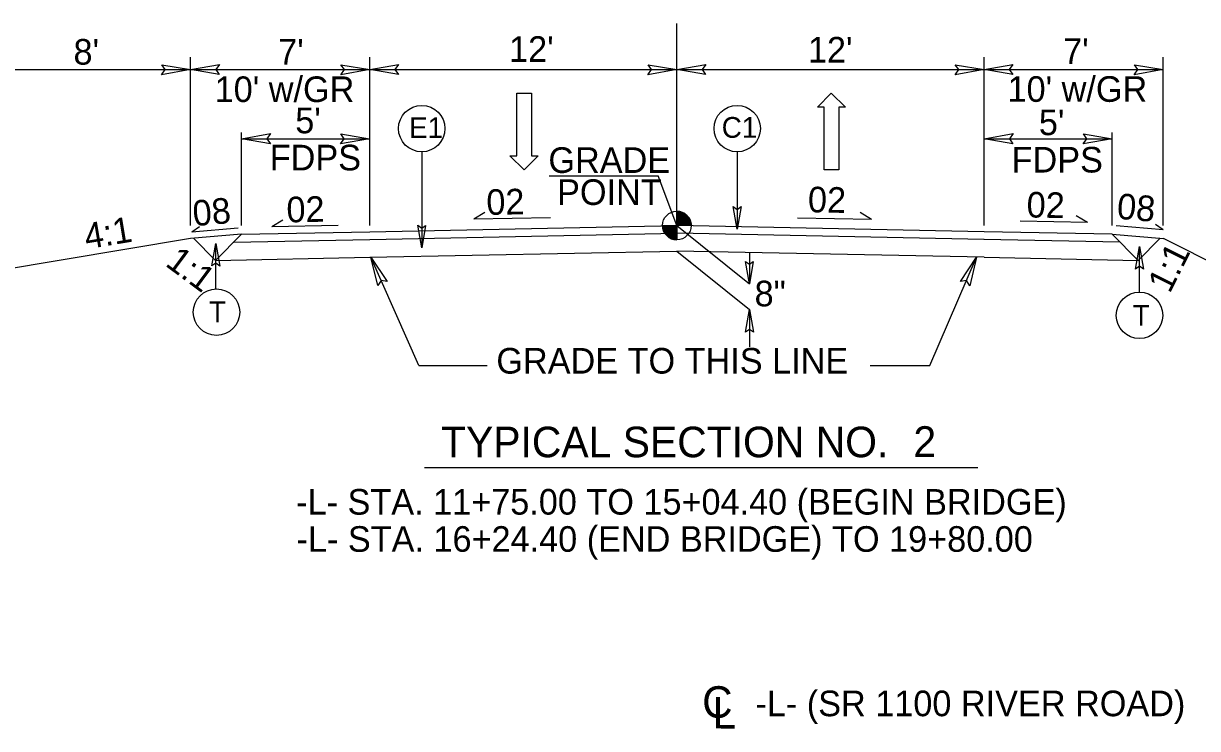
# Model space of a CAD drawing. Extents: x 1734085 to 1734267, y 541107 to 541226.
# Drawn here: x 1734191.61 to 1734237.47, y 541147.35 to 541174.87 of the extents above; entities that cross this region are included whole.
import ezdxf

# ---------------------------------------------------------------- set-up
doc = ezdxf.new("R2010")
doc.units = 0
for name, color, linetype in [('Prop Dimension', 7, 'Continuous'), ('Prop Lane Arrow CELL', 7, 'Continuous'), ('Prop Terminator CELL', 7, 'Continuous'), ('Typical Grade Point Symbol CELL', 7, 'Continuous'), ('Typical ID Circle CELL', 7, 'Continuous'), ('Typical Pavement Slope CELL', 7, 'Continuous'), ('Typical Pavement Slope Information CELL', 7, 'Continuous'), ('Typical Shoulder Slope CELL', 7, 'Continuous'), ('Typical Shoulder Slope Information CELL', 7, 'Continuous'), ('Typical Slope Point Local CELL', 7, 'Continuous'), ('Typical Terminator CELL', 7, 'Continuous'), ('Typical Text Centerline CELL', 7, 'Continuous'), ('Typical Text General CELL', 7, 'Continuous'), ('Typical Text Grade Point CELL', 7, 'Continuous'), ('Typical Text ID Circle CELL', 7, 'Continuous'), ('Typical Text Label CELL', 7, 'Continuous')]:
    doc.layers.add(name, color=color, linetype=linetype)

msp = doc.modelspace()

# ---------------------------------------------------------------- linework, layer by layer
at = {"layer": 'Prop Dimension'}
for p, q in [((1734217.135, 541166.983), (1734217.135, 541174.87)), ((1734198.135, 541166.983), (1734198.135, 541173.56)), ((1734205.135, 541166.983), (1734205.135, 541173.56)), ((1734229.135, 541166.983), (1734229.135, 541173.56)), ((1734236.135, 541166.983), (1734236.135, 541173.56)), ((1734190.135, 541173.068), (1734198.135, 541173.068)), ((1734198.135, 541173.068), (1734205.135, 541173.068)), ((1734205.135, 541173.068), (1734217.135, 541173.068)), ((1734217.135, 541173.068), (1734229.135, 541173.068)), ((1734229.135, 541173.068), (1734236.135, 541173.068)), ((1734200.13, 541166.983), (1734200.13, 541170.621)), ((1734234.139, 541166.983), (1734234.139, 541170.621)), ((1734200.13, 541170.371), (1734205.13, 541170.371)), ((1734229.139, 541170.371), (1734234.139, 541170.371)), ((1734212.149, 541168.921), (1734216.4, 541168.921)), ((1734217.135, 541166.983), (1734216.4, 541168.921)), ((1734217.135, 541166.983), (1734219.968, 541164.701)), ((1734207.055, 541161.522), (1734205.177, 541165.744)), ((1734217.135, 541165.983), (1734219.968, 541163.701)), ((1734219.968, 541165.907), (1734219.968, 541164.701)), ((1734227.019, 541161.524), (1734228.846, 541165.749)), ((1734219.968, 541163.701), (1734219.968, 541162.248)), ((1734207.055, 541161.522), (1734209.726, 541161.522)), ((1734224.683, 541161.524), (1734227.019, 541161.524))]:
    msp.add_line(p, q, dxfattribs=at)
at = {"layer": 'Prop Lane Arrow CELL'}
for p, q in [((1734210.879, 541169.704), (1734210.879, 541172.154)), ((1734210.879, 541172.154), (1734211.456, 541172.154)), ((1734211.456, 541172.154), (1734211.456, 541169.704)), ((1734222.624, 541171.602), (1734223.166, 541172.153)), ((1734223.166, 541172.153), (1734223.726, 541171.602)), ((1734222.886, 541171.602), (1734222.624, 541171.602)), ((1734222.886, 541169.152), (1734222.886, 541171.602)), ((1734223.726, 541171.602), (1734223.464, 541171.602)), ((1734223.464, 541171.602), (1734223.464, 541169.152)), ((1734211.176, 541169.153), (1734210.616, 541169.704)), ((1734210.616, 541169.704), (1734210.879, 541169.704)), ((1734211.719, 541169.704), (1734211.176, 541169.153)), ((1734211.456, 541169.704), (1734211.719, 541169.704)), ((1734223.464, 541169.152), (1734222.886, 541169.152))]:
    msp.add_line(p, q, dxfattribs=at)
at = {"layer": 'Prop Terminator CELL'}
for points in [[(1734197.01, 541173.262), (1734198.135, 541173.068), (1734197.003, 541172.868), (1734197.147, 541173.068)], [(1734199.26, 541172.874), (1734198.135, 541173.068), (1734199.266, 541173.268), (1734199.122, 541173.068)], [(1734204.01, 541173.262), (1734205.135, 541173.068), (1734204.003, 541172.868), (1734204.147, 541173.068)], [(1734206.26, 541172.874), (1734205.135, 541173.068), (1734206.266, 541173.268), (1734206.122, 541173.068)], [(1734216.01, 541173.262), (1734217.135, 541173.068), (1734216.003, 541172.868), (1734216.147, 541173.068)], [(1734218.26, 541172.874), (1734217.135, 541173.068), (1734218.266, 541173.268), (1734218.122, 541173.068)], [(1734228.01, 541173.262), (1734229.135, 541173.068), (1734228.003, 541172.868), (1734228.147, 541173.068)], [(1734230.26, 541172.874), (1734229.135, 541173.068), (1734230.266, 541173.268), (1734230.122, 541173.068)], [(1734235.01, 541173.262), (1734236.135, 541173.068), (1734235.003, 541172.868), (1734235.147, 541173.068)], [(1734201.255, 541170.177), (1734200.13, 541170.371), (1734201.262, 541170.571), (1734201.118, 541170.371)], [(1734204.005, 541170.565), (1734205.13, 541170.371), (1734203.999, 541170.171), (1734204.143, 541170.371)], [(1734230.264, 541170.177), (1734229.139, 541170.371), (1734230.27, 541170.571), (1734230.127, 541170.371)], [(1734233.014, 541170.565), (1734234.139, 541170.371), (1734233.008, 541170.171), (1734233.152, 541170.371)], [(1734205.457, 541164.637), (1734205.177, 541165.744), (1734205.819, 541164.792), (1734205.578, 541164.842)], [(1734228.221, 541164.793), (1734228.846, 541165.749), (1734228.58, 541164.631), (1734228.454, 541164.842)]]:
    msp.add_lwpolyline(points, close=True, dxfattribs=at)
at = {"layer": 'Typical Grade Point Symbol CELL'}
for p, q in [((1734217.135, 541166.983), (1734217.135, 541167.543)), ((1734216.575, 541166.983), (1734217.135, 541166.983)), ((1734217.133, 541166.424), (1734217.135, 541166.983)), ((1734217.135, 541166.983), (1734217.133, 541166.424)), ((1734217.694, 541166.983), (1734217.135, 541166.983))]:
    msp.add_line(p, q, dxfattribs=at)
for points in [[(1734217.14, 541167.543), (1734217.14, 541167.543), (1734217.14, 541166.983)], [(1734217.151, 541167.543), (1734217.151, 541166.983)], [(1734217.162, 541167.541), (1734217.162, 541166.983)], [(1734217.173, 541167.541), (1734217.173, 541166.983)], [(1734217.184, 541167.54), (1734217.184, 541166.983)], [(1734217.196, 541167.539), (1734217.196, 541166.983)], [(1734217.207, 541167.538), (1734217.207, 541166.983)], [(1734217.218, 541167.536), (1734217.218, 541166.983)], [(1734217.229, 541167.535), (1734217.229, 541166.983)], [(1734217.24, 541167.533), (1734217.24, 541166.983)], [(1734217.252, 541167.53), (1734217.252, 541166.983)], [(1734217.263, 541167.528), (1734217.263, 541166.983)], [(1734217.274, 541167.525), (1734217.274, 541166.983)], [(1734217.285, 541167.522), (1734217.285, 541166.983)], [(1734217.296, 541167.519), (1734217.296, 541166.983)], [(1734217.308, 541167.515), (1734217.308, 541166.983)], [(1734217.319, 541167.512), (1734217.319, 541166.983)], [(1734217.33, 541167.508), (1734217.33, 541166.983)], [(1734217.341, 541167.503), (1734217.341, 541166.983)], [(1734217.352, 541167.498), (1734217.352, 541166.983)], [(1734217.364, 541167.493), (1734217.364, 541166.983)], [(1734217.375, 541167.488), (1734217.375, 541166.983)], [(1734217.386, 541167.483), (1734217.386, 541166.983)], [(1734217.397, 541167.477), (1734217.397, 541166.983)], [(1734217.408, 541167.471), (1734217.408, 541166.983)], [(1734217.419, 541167.464), (1734217.419, 541166.983)], [(1734217.431, 541167.458), (1734217.431, 541166.983)], [(1734217.442, 541167.451), (1734217.442, 541166.983)], [(1734217.453, 541167.443), (1734217.453, 541166.983)], [(1734217.464, 541167.435), (1734217.464, 541166.983)], [(1734217.475, 541167.427), (1734217.475, 541166.983)], [(1734217.487, 541167.418), (1734217.487, 541166.983)], [(1734217.498, 541167.408), (1734217.498, 541166.983)], [(1734217.509, 541167.398), (1734217.509, 541166.983)], [(1734217.52, 541167.388), (1734217.52, 541166.983)], [(1734216.578, 541166.983), (1734216.578, 541166.922)], [(1734216.589, 541166.983), (1734216.589, 541166.856)], [(1734216.6, 541166.983), (1734216.6, 541166.817)], [(1734216.611, 541166.983), (1734216.611, 541166.783)], [(1734216.623, 541166.983), (1734216.623, 541166.757)], [(1734216.634, 541166.983), (1734216.634, 541166.733)], [(1734216.645, 541166.983), (1734216.645, 541166.712)], [(1734216.656, 541166.983), (1734216.656, 541166.692)], [(1734216.667, 541166.983), (1734216.667, 541166.675)], [(1734216.678, 541166.983), (1734216.678, 541166.659)], [(1734216.69, 541166.983), (1734216.69, 541166.644)], [(1734216.701, 541166.983), (1734216.701, 541166.63)], [(1734216.712, 541166.983), (1734216.712, 541166.616)], [(1734216.723, 541166.983), (1734216.723, 541166.604)], [(1734216.734, 541166.983), (1734216.734, 541166.592)], [(1734216.746, 541166.983), (1734216.746, 541166.58)], [(1734216.757, 541166.983), (1734216.757, 541166.57)], [(1734216.768, 541166.983), (1734216.768, 541166.56)], [(1734216.779, 541166.983), (1734216.779, 541166.551)], [(1734216.79, 541166.983), (1734216.79, 541166.542)], [(1734216.802, 541166.983), (1734216.802, 541166.533)], [(1734216.813, 541166.983), (1734216.813, 541166.526)], [(1734216.824, 541166.983), (1734216.824, 541166.518)], [(1734216.835, 541166.983), (1734216.835, 541166.511)], [(1734216.846, 541166.983), (1734216.846, 541166.503)], [(1734216.857, 541166.983), (1734216.857, 541166.497)], [(1734216.869, 541166.983), (1734216.869, 541166.491)], [(1734216.88, 541166.983), (1734216.88, 541166.485)], [(1734216.891, 541166.983), (1734216.891, 541166.48)], [(1734216.902, 541166.983), (1734216.902, 541166.475)], [(1734216.913, 541166.983), (1734216.913, 541166.47)], [(1734216.925, 541166.983), (1734216.925, 541166.465)], [(1734216.936, 541166.983), (1734216.936, 541166.46)], [(1734216.947, 541166.983), (1734216.947, 541166.456)], [(1734216.958, 541166.983), (1734216.958, 541166.452)], [(1734216.969, 541166.983), (1734216.969, 541166.449)], [(1734216.981, 541166.983), (1734216.981, 541166.446)], [(1734216.992, 541166.983), (1734216.992, 541166.442)], [(1734217.003, 541166.983), (1734217.003, 541166.44)], [(1734217.014, 541166.983), (1734217.014, 541166.437)], [(1734217.025, 541166.983), (1734217.025, 541166.435)], [(1734217.036, 541166.983), (1734217.036, 541166.432)], [(1734217.048, 541166.983), (1734217.048, 541166.431)], [(1734217.059, 541166.983), (1734217.059, 541166.429)], [(1734217.07, 541166.983), (1734217.07, 541166.427)], [(1734217.081, 541166.983), (1734217.081, 541166.426)], [(1734217.092, 541166.983), (1734217.092, 541166.425)], [(1734217.104, 541166.983), (1734217.104, 541166.425)], [(1734217.115, 541166.983), (1734217.115, 541166.424)], [(1734217.126, 541166.983), (1734217.126, 541166.424), (1734217.126, 541166.424)], [(1734217.531, 541167.377), (1734217.531, 541166.983)], [(1734217.543, 541167.366), (1734217.543, 541166.983)], [(1734217.554, 541167.354), (1734217.554, 541166.983)], [(1734217.565, 541167.34), (1734217.565, 541166.983)], [(1734217.576, 541167.326), (1734217.576, 541166.983)], [(1734217.587, 541167.311), (1734217.587, 541166.983)], [(1734217.599, 541167.295), (1734217.599, 541166.983)], [(1734217.61, 541167.278), (1734217.61, 541166.983)], [(1734217.621, 541167.259), (1734217.621, 541166.983)], [(1734217.632, 541167.239), (1734217.632, 541166.983)], [(1734217.643, 541167.216), (1734217.643, 541166.983)], [(1734217.654, 541167.19), (1734217.654, 541166.983)], [(1734217.666, 541167.158), (1734217.666, 541166.983)], [(1734217.677, 541167.12), (1734217.677, 541166.983)], [(1734217.688, 541167.063), (1734217.688, 541166.983)]]:
    msp.add_lwpolyline(points, dxfattribs=at)
msp.add_circle((1734217.134, 541166.983), 0.559, dxfattribs=at)
for start, end in [(359.9905, 89.9905), (179.9905, 269.9905)]:
    msp.add_arc((1734217.134, 541166.983), 0.559, start, end, dxfattribs=at)
at = {"layer": 'Typical ID Circle CELL'}
for p, q in [((1734207.168, 541169.861), (1734207.168, 541166.109)), ((1734219.493, 541169.861), (1734219.493, 541166.841)), ((1734199.12, 541164.507), (1734199.12, 541166.286)), ((1734235.208, 541164.384), (1734235.208, 541166.163))]:
    msp.add_line(p, q, dxfattribs=at)
for centre in [(1734207.168, 541170.767), (1734219.493, 541170.767), (1734199.152, 541163.601), (1734235.208, 541163.477)]:
    msp.add_circle(centre, 0.906, dxfattribs=at)
at = {"layer": 'Typical Pavement Slope CELL'}
for p, q in [((1734205.135, 541166.743), (1734217.135, 541166.983)), ((1734229.135, 541166.743), (1734217.135, 541166.983)), ((1734200.13, 541166.641), (1734198.13, 541166.474)), ((1734205.135, 541166.443), (1734217.141, 541166.683)), ((1734229.135, 541166.443), (1734217.129, 541166.683)), ((1734234.139, 541166.641), (1734236.14, 541166.474)), ((1734199.112, 541165.623), (1734205.135, 541165.743)), ((1734205.135, 541165.743), (1734217.135, 541165.983)), ((1734229.135, 541165.743), (1734217.135, 541165.983)), ((1734229.135, 541165.743), (1734235.157, 541165.623))]:
    msp.add_line(p, q, dxfattribs=at)
at = {"layer": 'Typical Pavement Slope Information CELL'}
for p, q in [((1734209.202, 541167.239), (1734209.639, 541167.504)), ((1734224.745, 541167.218), (1734224.296, 541167.49)), ((1734198.19, 541166.735), (1734198.482, 541166.94)), ((1734201.309, 541166.939), (1734201.747, 541167.203)), ((1734201.309, 541166.939), (1734203.909, 541166.991)), ((1734209.202, 541167.239), (1734212.193, 541167.299)), ((1734224.745, 541167.218), (1734221.851, 541167.276)), ((1734233.182, 541167.095), (1734230.542, 541167.148)), ((1734233.182, 541167.095), (1734232.733, 541167.366)), ((1734236.132, 541166.81), (1734234.294, 541166.965)), ((1734236.132, 541166.81), (1734235.831, 541167.019)), ((1734198.19, 541166.735), (1734199.999, 541166.896))]:
    msp.add_line(p, q, dxfattribs=at)
at = {"layer": 'Typical Shoulder Slope CELL'}
for p, q in [((1734198.25, 541166.484), (1734199.112, 541165.622)), ((1734200.13, 541166.641), (1734199.112, 541165.622)), ((1734200.13, 541166.641), (1734205.135, 541166.743)), ((1734234.139, 541166.641), (1734229.135, 541166.743)), ((1734234.139, 541166.641), (1734235.158, 541165.622)), ((1734236.02, 541166.484), (1734235.158, 541165.622)), ((1734199.824, 541166.334), (1734205.141, 541166.443)), ((1734234.445, 541166.334), (1734229.129, 541166.443))]:
    msp.add_line(p, q, dxfattribs=at)
at = {"layer": 'Typical Slope Point Local CELL'}
for p, q in [((1734198.13, 541166.474), (1734190.13, 541165.141)), ((1734251.137, 541158.975), (1734236.14, 541166.474))]:
    msp.add_line(p, q, dxfattribs=at)
at = {"layer": 'Typical Terminator CELL'}
for points in [[(1734219.644, 541167.72), (1734219.493, 541166.841), (1734219.337, 541167.724), (1734219.493, 541167.612)], [(1734207.32, 541166.988), (1734207.168, 541166.109), (1734207.012, 541166.993), (1734207.168, 541166.88)], [(1734198.969, 541165.407), (1734199.12, 541166.286), (1734199.276, 541165.403), (1734199.12, 541165.515)], [(1734235.056, 541165.284), (1734235.208, 541166.163), (1734235.364, 541165.28), (1734235.208, 541165.392)], [(1734220.119, 541165.58), (1734219.968, 541164.701), (1734219.812, 541165.585), (1734219.968, 541165.472)], [(1734219.816, 541162.822), (1734219.968, 541163.701), (1734220.124, 541162.817), (1734219.968, 541162.929)]]:
    msp.add_lwpolyline(points, close=True, dxfattribs=at)
at = {"layer": 'Typical Text Label CELL'}
msp.add_line((1734207.283, 541157.537), (1734228.888, 541157.537), dxfattribs=at)

# ---------------------------------------------------------------- texts
at = {"layer": 'Typical Pavement Slope Information CELL'}
for rotation, p in [(1.1457, (1734209.703, 541167.394)), (358.8543, (1734222.248, 541167.503))]:
    msp.add_text('02', height=1, rotation=rotation, dxfattribs=at).set_placement(p)
at = {"layer": 'Typical Shoulder Slope Information CELL'}
for s, rotation, p in [('02', 358.8543, (1734230.791, 541167.301)), ('08', 5.1049, (1734198.265, 541166.954)), ('02', 1.1457, (1734201.894, 541167.103)), ('08', 355.1872, (1734234.298, 541167.25))]:
    msp.add_text(s, height=1, rotation=rotation, dxfattribs=at).set_placement(p)
at = {"layer": 'Typical Slope Point Local CELL'}
for s, rotation, p in [("8'", 360, (1734193.566, 541173.264)), ("7'", 360, (1734201.561, 541173.264)), ("12'", 360, (1734210.581, 541173.373)), ("12'", 360, (1734222.255, 541173.346)), ("7'", 360, (1734232.224, 541173.289)), ("10' w/GR", 360, (1734199.08, 541171.804)), ("10' w/GR", 360, (1734230.053, 541171.812)), ("5'", 360, (1734202.228, 541170.583)), ("5'", 360, (1734231.277, 541170.511)), ('FDPS', 360, (1734201.231, 541169.136)), ('FDPS', 360, (1734230.212, 541169.053)), ('4:1', 9.4623, (1734194.076, 541166.055)), ('1:1', 323.3821, (1734197.111, 541165.437)), ('1:1', 63.4349, (1734236.385, 541164.298)), ('8"', 360, (1734220.172, 541163.828))]:
    msp.add_text(s, height=1, rotation=rotation, dxfattribs=at).set_placement(p)
at = {"layer": 'Typical Text Centerline CELL'}
for s, height, p in [('C', 1.23, (1734218.124, 541147.768)), ('-L- (SR 1100 RIVER ROAD)', 1, (1734220.205, 541147.827))]:
    msp.add_text(s, height=height, dxfattribs=at).set_placement(p)
msp.add_text('L', height=1.231, rotation=359.9469, dxfattribs=at).set_placement((1734218.533, 541147.348))
at = {"layer": 'Typical Text General CELL'}
msp.add_text('GRADE TO THIS LINE', height=1, dxfattribs=at).set_placement((1734210.084, 541161.203))
at = {"layer": 'Typical Text Grade Point CELL'}
for s, p in [('GRADE', (1734212.117, 541169.037)), ('POINT', (1734212.456, 541167.786))]:
    msp.add_text(s, height=1, dxfattribs=at).set_placement(p)
at = {"layer": 'Typical Text ID Circle CELL'}
for s, height, p in [('E1', 0.8112, (1734206.678, 541170.4)), ('C1', 0.8112, (1734218.888, 541170.408)), ('T', 0.811, (1734198.86, 541163.21)), ('T', 0.811, (1734234.941, 541163.072))]:
    msp.add_text(s, height=height, dxfattribs=at).set_placement(p)
at = {"layer": 'Typical Text Label CELL'}
for s, height, p in [('TYPICAL SECTION NO.  ', 1.19356, (1734207.924, 541157.937)), ('2', 1.194, (1734226.376, 541157.953)), ('-L- STA. 11+75.00 TO 15+04.40 (BEGIN BRIDGE)', 1, (1734202.265, 541155.697)), ('-L- STA. 16+24.40 (END BRIDGE) TO 19+80.00', 1, (1734202.278, 541154.246))]:
    msp.add_text(s, height=height, dxfattribs=at).set_placement(p)

doc.saveas('drawing.dxf')
